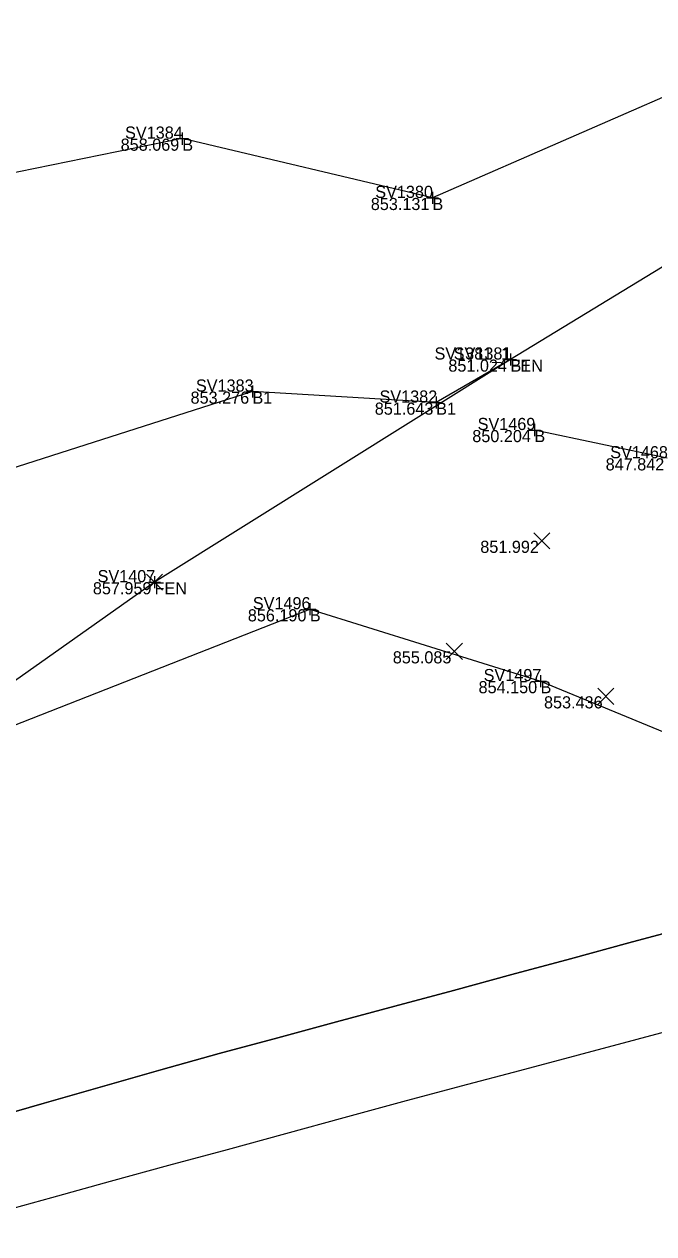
# Model space of a CAD drawing. Extents: x 2125299 to 2129212, y 713100 to 714300.
# Drawn here: x 2128261.4 to 2128313.4, y 713795.4 to 713895.2 of the extents above; entities that cross this region are included whole.
import ezdxf

# ---------------------------------------------------------------- set-up
doc = ezdxf.new("R2010")
doc.units = 0
for name, color, linetype in [('Default', 7, 'Continuous'), ('DT_X_Terrain_Boundary', 7, 'Continuous'), ('PV_X_Field_Drive', 7, 'Continuous'), ('RD_X_Fence', 7, 'Continuous'), ('RW_P_Esmt_TMP', 7, 'Continuous'), ('RW_X_Esmt_CH', 7, 'Continuous'), ('RW_X_Fee_WL', 7, 'Continuous'), ('SV_X_Break_Lines', 7, 'Continuous'), ('SV_X_Mon_Cells_Found', 7, 'Continuous'), ('SV_X_Text_Elevation', 7, 'Continuous')]:
    doc.layers.add(name, color=color, linetype=linetype)

msp = doc.modelspace()

# ---------------------------------------------------------------- linework, layer by layer
at = {"layer": 'Default'}
msp.add_lwpolyline([(2128249.081, 713832.867), (2128285.007, 713846.966), (2128304.036, 713841.037), (2128326.028, 713831.967), (2128330.637, 713824.65), (2128325.81, 713823.347), (2128320.983, 713822.043), (2128316.156, 713820.739), (2128311.329, 713819.435), (2128306.502, 713818.131), (2128301.675, 713816.827), (2128296.848, 713815.523), (2128292.021, 713814.219), (2128287.194, 713812.915), (2128282.367, 713811.611), (2128277.54, 713810.307), (2128272.721, 713808.974), (2128267.915, 713807.594), (2128263.109, 713806.214), (2128258.304, 713804.834)], dxfattribs=at)
at = {"layer": 'DT_X_Terrain_Boundary'}
msp.add_lwpolyline([(2128258.92, 713797.1), (2128263.737, 713798.44), (2128268.556, 713799.771), (2128273.38, 713801.088), (2128278.203, 713802.404), (2128283.027, 713803.721), (2128287.85, 713805.038), (2128292.676, 713806.345), (2128297.508, 713807.631), (2128302.34, 713808.917), (2128307.172, 713810.202), (2128312.004, 713811.488), (2128316.836, 713812.774)], dxfattribs=at)
at = {"layer": 'PV_X_Field_Drive'}
for points in [[(2128258.304, 713804.834), (2128263.109, 713806.214), (2128267.915, 713807.594), (2128272.721, 713808.974), (2128277.54, 713810.307), (2128282.367, 713811.611), (2128287.194, 713812.915), (2128292.021, 713814.219), (2128296.848, 713815.523), (2128301.675, 713816.827), (2128306.502, 713818.131), (2128311.329, 713819.435), (2128316.156, 713820.739)], [(2128258.92, 713797.1), (2128263.737, 713798.44), (2128268.556, 713799.771), (2128273.38, 713801.088), (2128278.203, 713802.404), (2128283.027, 713803.721), (2128287.85, 713805.038), (2128292.676, 713806.345), (2128297.508, 713807.631), (2128302.34, 713808.917), (2128307.172, 713810.202), (2128312.004, 713811.488), (2128316.836, 713812.774)]]:
    msp.add_lwpolyline(points, dxfattribs=at)
at = {"layer": 'RD_X_Fence'}
msp.add_lwpolyline([(2128324.526, 713881.58), (2128301.553, 713867.571), (2128272.196, 713849.199), (2128249.081, 713832.867), (2128213.094, 713823.853), (2128180.679, 713818.154), (2128133.829, 713809.764), (2128103.722, 713804.695), (2128050.486, 713795.434)], dxfattribs=at)
at = {"layer": 'SV_X_Break_Lines'}
for points in [[(2128473.365, 713923.912), (2128453.453, 713915.843), (2128410.188, 713893.98), (2128387.409, 713892.535), (2128363.211, 713893.719), (2128345.595, 713896.5), (2128318.819, 713891.258), (2128295.116, 713880.906), (2128274.488, 713885.799), (2128242.12, 713879.196), (2128218.829, 713874.939), (2128184.367, 713862.099), (2128151.548, 713852.787), (2128121.592, 713848.655), (2128121.634, 713848.486), (2128085.287, 713843.491), (2128066.442, 713838.356)], [(2128362.17, 713888.596), (2128349.078, 713887.908), (2128324.526, 713881.58), (2128301.553, 713867.571), (2128295.426, 713864.02), (2128280.273, 713864.928), (2128247.092, 713854.317), (2128208.777, 713841.528), (2128155.39, 713832.168), (2128105.372, 713824.737)], [(2128285.007, 713846.966), (2128304.036, 713841.037), (2128326.028, 713831.967), (2128335.229, 713829.953), (2128351.209, 713834.175), (2128372.654, 713840.365), (2128397.041, 713854.87), (2128424.528, 713863.803), (2128437.965, 713867.069)], [(2128314.478, 713859.425), (2128303.528, 713861.756)]]:
    msp.add_lwpolyline(points, dxfattribs=at)
at = {"layer": 'SV_X_Mon_Cells_Found'}
for p, q in [((2128273.988, 713885.799), (2128274.988, 713885.799)), ((2128274.488, 713886.299), (2128274.488, 713885.299)), ((2128274.488, 713885.799), (2128274.488, 713885.799)), ((2128295.116, 713881.406), (2128295.116, 713880.406)), ((2128294.616, 713880.906), (2128295.616, 713880.906)), ((2128295.116, 713880.906), (2128295.116, 713880.906)), ((2128301.053, 713867.571), (2128302.053, 713867.571)), ((2128301.053, 713867.571), (2128302.053, 713867.571)), ((2128301.553, 713868.071), (2128301.553, 713867.071)), ((2128301.553, 713868.071), (2128301.553, 713867.071)), ((2128301.553, 713867.571), (2128301.553, 713867.571)), ((2128301.553, 713867.571), (2128301.553, 713867.571)), ((2128280.273, 713865.428), (2128280.273, 713864.428)), ((2128279.773, 713864.928), (2128280.773, 713864.928)), ((2128280.273, 713864.928), (2128280.273, 713864.928)), ((2128295.426, 713864.52), (2128295.426, 713863.52)), ((2128294.926, 713864.02), (2128295.926, 713864.02)), ((2128295.426, 713864.02), (2128295.426, 713864.02)), ((2128303.028, 713861.756), (2128304.028, 713861.756)), ((2128303.528, 713862.256), (2128303.528, 713861.256)), ((2128303.528, 713861.756), (2128303.528, 713861.756)), ((2128272.196, 713849.699), (2128272.196, 713848.699)), ((2128271.696, 713849.199), (2128272.696, 713849.199)), ((2128272.196, 713849.199), (2128272.196, 713849.199)), ((2128285.007, 713847.466), (2128285.007, 713846.466)), ((2128284.507, 713846.966), (2128285.507, 713846.966)), ((2128285.007, 713846.966), (2128285.007, 713846.966)), ((2128304.036, 713841.537), (2128304.036, 713840.537)), ((2128303.536, 713841.037), (2128304.536, 713841.037)), ((2128304.036, 713841.037), (2128304.036, 713841.037))]:
    msp.add_line(p, q, dxfattribs=at)
at = {"layer": 'SV_X_Text_Elevation'}
for p, q in [((2128303.472, 713851.95), (2128304.806, 713853.285)), ((2128303.472, 713853.285), (2128304.806, 713851.95)), ((2128271.529, 713848.531), (2128272.863, 713849.866)), ((2128271.529, 713849.866), (2128272.863, 713848.531)), ((2128296.251, 713842.833), (2128297.585, 713844.168)), ((2128296.251, 713844.168), (2128297.585, 713842.833)), ((2128308.757, 713839.119), (2128310.091, 713840.454)), ((2128308.757, 713840.454), (2128310.091, 713839.119))]:
    msp.add_line(p, q, dxfattribs=at)

# ---------------------------------------------------------------- texts
at = {"layer": 'RW_P_Esmt_TMP'}
for s, p in [('B', (2128274.488, 713884.799)), ('B', (2128295.116, 713879.906)), ('FEN', (2128301.553, 713866.571)), ('B1', (2128301.553, 713866.571)), ('B1', (2128280.273, 713863.928)), ('B1', (2128295.426, 713863.02)), ('B', (2128303.528, 713860.756)), ('FEN', (2128272.196, 713848.199)), ('B', (2128285.007, 713845.966)), ('B', (2128304.036, 713840.037))]:
    msp.add_text(s, height=1, dxfattribs=at).set_placement(p)
at = {"layer": 'RW_X_Esmt_CH'}
for s, p in [('SV1384', (2128269.768, 713885.799)), ('SV1380', (2128290.404, 713880.906)), ('SV1381_1', (2128295.29, 713867.571)), ('SV1381', (2128296.873, 713867.571)), ('SV1383', (2128275.611, 713864.928)), ('SV1382', (2128290.755, 713864.02)), ('SV1469', (2128298.846, 713861.756)), ('SV1468', (2128309.779, 713859.425)), ('SV1407', (2128267.502, 713849.199)), ('SV1496', (2128280.305, 713846.966)), ('SV1497', (2128299.342, 713841.037))]:
    msp.add_text(s, height=1, dxfattribs=at).set_placement(p)
at = {"layer": 'RW_X_Fee_WL'}
for s, p in [('858.069', (2128269.404, 713884.799)), ('853.131', (2128290.034, 713879.906)), ('851.024', (2128296.431, 713866.571)), ('851.024', (2128296.431, 713866.571)), ('853.276', (2128275.169, 713863.928)), ('851.643', (2128290.362, 713863.02)), ('850.204', (2128298.406, 713860.756)), ('847.842', (2128309.405, 713858.425)), ('851.992', (2128299.066, 713851.617)), ('857.959', (2128267.112, 713848.199)), ('857.959', (2128267.112, 713848.199)), ('856.190', (2128279.893, 713845.966)), ('855.085', (2128291.848, 713842.501)), ('854.150', (2128298.922, 713840.037)), ('853.436', (2128304.32, 713838.787))]:
    msp.add_text(s, height=1, dxfattribs=at).set_placement(p)

doc.saveas('drawing.dxf')
